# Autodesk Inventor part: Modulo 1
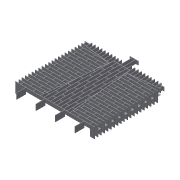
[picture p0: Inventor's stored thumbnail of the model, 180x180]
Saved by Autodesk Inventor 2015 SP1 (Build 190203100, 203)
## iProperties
Created: 2015-04
Part Number: Modulo 1
Material: Generic
Document SubType Name: Modeling
Designer: treina2
Density: 1 g/cm^3
Appearance: Default
Author: treina2
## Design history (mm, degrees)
sketch "Sketch1"
  geometry: L1 (1091.806, 200)-(1091.806, 440) reference; L2 (1091.806, 440)-(1033.806, 440) reference; L3 (1033.806, 440)-(1033.806, 200) reference; L4 (1033.806, 200)-(1091.806, 200) reference; L5 (1159.806, 200)-(1159.806, 315) reference; L6 (1159.806, 315)-(1101.806, 315) reference; L7 (1101.806, 315)-(1101.806, 200) reference; L8 (1101.806, 200)-(1159.806, 200) reference; L9 (1227.806, 200)-(1227.806, 440) reference; L10 (1227.806, 440)-(1169.806, 440) reference; L11 (1169.806, 440)-(1169.806, 200) reference; L12 (1169.806, 200)-(1227.806, 200) reference; L13 (1024, 200)-(1024, 315) reference; L14 (1024, 315)-(966, 315) reference; L15 (966, 315)-(966, 200) reference; L16 (966, 200)-(1024, 200) reference; L17 (1169.806, 1464.632)-(1169.806, 1450) reference; L18 (1169.806, 1450)-(1171.263, 1450) reference; L19 (1284.348, 315)-(1237.806, 315) reference; L20 (1237.806, 315)-(1237.806, 200) reference; L21 (1237.806, 200)-(1295.806, 200) reference; L22 (1259.439, 565)-(1283.351, 325) reference; L23 (1259.439, 565)-(1237.806, 565) reference; L24 (1237.806, 565)-(1237.806, 325) reference; L25 (1237.806, 325)-(1283.351, 325) reference; L26 (1169.806, 1565)-(1177.128, 1492) reference; L27 (1237.806, 1498.938)-(1295.806, 1505.57) reference; L28 (1295.806, 1505.57)-(1295.806, 1686) reference; L29 (1295.806, 1686)-(1237.806, 1686) reference; L30 (1237.806, 1686)-(1237.806, 1498.938) reference; L31 (1159.806, 325)-(1159.806, 565) reference; L32 (1159.806, 565)-(1101.806, 565) reference; L33 (1101.806, 565)-(1101.806, 325) reference; L34 (1101.806, 325)-(1159.806, 325) reference; L35 (1703.806, 1552.224)-(1703.806, 1686) reference; L36 (1703.806, 1686)-(1645.806, 1686) reference; L37 (1645.806, 1686)-(1645.806, 1545.592) reference; L38 (1024, 325)-(1024, 565) reference; L39 (1024, 565)-(966, 565) reference; L40 (966, 565)-(966, 325) reference; L41 (966, 325)-(1024, 325) reference; L42 (1091.806, 450)-(1091.806, 690) reference; L43 (1091.806, 690)-(1033.806, 690) reference; L44 (1033.806, 690)-(1033.806, 450) reference; L45 (1033.806, 450)-(1091.806, 450) reference; L46 (1227.806, 450)-(1227.806, 690) reference; L47 (1227.806, 690)-(1169.806, 690) reference; L48 (1169.806, 690)-(1169.806, 450) reference; L49 (1169.806, 450)-(1227.806, 450) reference; L50 (1159.806, 575)-(1159.806, 815) reference; L51 (1159.806, 815)-(1101.806, 815) reference; L52 (1101.806, 815)-(1101.806, 575) reference; L53 (1101.806, 575)-(1159.806, 575) reference; L54 (1237.806, 782.132)-(1237.806, 575) reference; L55 (1237.806, 575)-(1258.443, 575) reference; L56 (1024, 575)-(1024, 815) reference; L57 (1024, 815)-(966, 815) reference; L58 (966, 815)-(966, 575) reference; L59 (966, 575)-(1024, 575) reference; L60 (1091.806, 700)-(1091.806, 940) reference; L61 (1091.806, 940)-(1033.806, 940) reference; L62 (1033.806, 940)-(1033.806, 700) reference; L63 (1033.806, 700)-(1091.806, 700) reference; L64 (1227.806, 700)-(1227.806, 882.5) reference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; 1 further point
  constraints: 1754 end point, 397 horizontal, 367 vertical, 18 point on line, 953 other
workplane "Work Plane1"
sketch "Sketch2"
  geometry: L1 (1990, 0)-(1600, 0) reference; L2 (1990, 0)-(1880.303, 190) reference; L3 (1765, 190)-(1880.303, 190) reference; L4 (1600, 190)-(1880.303, 190) reference; L5 (1600, 0)-(1600, 190) reference; L6 (1590, 190)-(1590, 0) reference; L7 (1200, 190)-(1590, 190) reference; L8 (1590, 0)-(1200, 0) reference; L9 (1200, 0)-(1200, 190) reference; L10 (1190, 190)-(1190, 0) reference; L11 (1190, 0)-(800, 0) reference; L12 (800, 190)-(1190, 190) reference; L13 (800, 0)-(800, 190) reference; L14 (790, 190)-(790, 0) reference; L15 (400, 190)-(790, 190) reference; L16 (790, 0)-(400, 0) reference; L17 (400, 0)-(400, 190) reference; L18 (390, 190)-(390, 0) reference; L19 (109.697, 190)-(390, 190) reference; L20 (390, 0)-(0, 0) reference; L21 (0, 0)-(109.697, 190) reference; 1 further point
extrude "Extrusion1" new body sketch "Sketch2" distance "d2" = 140 (= BLOCO_PADRAO_LARG); taper "d3" = 0 deg
extrude "Extrusion2" new body sketch "Sketch2" distance "d4" = 140 (= BLOCO_PADRAO_LARG); taper "d5" = 0 deg
extrude "Extrusion3" new body sketch "Sketch2" distance "d6" = 140 (= BLOCO_PADRAO_LARG); taper "d7" = 0 deg
extrude "Extrusion4" new body sketch "Sketch2" distance "d8" = 140 (= BLOCO_PADRAO_LARG); taper "d9" = 0 deg
extrude "Extrusion5" new body sketch "Sketch2" distance "d10" = 140 (= BLOCO_PADRAO_LARG); taper "d11" = 0 deg
extrude "Extrusion6" new body sketch "Sketch1" distance "d12" = 240 (= TIJOLO_PADRAO_COMP); taper "d13" = 0 deg
extrude "Extrusion7" new body sketch "Sketch1" distance "d14" = 240 (= TIJOLO_PADRAO_COMP); taper "d15" = 0 deg
extrude "Extrusion8" new body sketch "Sketch1" distance "d16" = 115 (= TIJOLO_PADRAO_LARG); taper "d17" = 0 deg
extrude "Extrusion9" new body sketch "Sketch1" distance "d18" = 115 (= TIJOLO_PADRAO_LARG); taper "d19" = 0 deg
extrude "Extrusion10" new body sketch "Sketch1" distance "d20" = 115 (= TIJOLO_PADRAO_LARG); taper "d21" = 0 deg
extrude "Extrusion11" new body sketch "Sketch1" distance "d22" = 115 (= TIJOLO_PADRAO_LARG); taper "d23" = 0 deg
extrude "Extrusion12" new body sketch "Sketch1" distance "d24" = 115 (= TIJOLO_PADRAO_LARG); taper "d25" = 0 deg
extrude "Extrusion13" new body sketch "Sketch1" distance "d26" = 240 (= TIJOLO_PADRAO_COMP); taper "d27" = 0 deg
extrude "Extrusion14" new body sketch "Sketch1" distance "d28" = 115 (= TIJOLO_PADRAO_LARG); taper "d29" = 0 deg
extrude "Extrusion15" new body sketch "Sketch1" distance "d30" = 115 (= TIJOLO_PADRAO_LARG); taper "d31" = 0 deg
extrude "Extrusion16" new body sketch "Sketch1" distance "d32" = 115 (= TIJOLO_PADRAO_LARG); taper "d33" = 0 deg
extrude "Extrusion17" new body sketch "Sketch1" distance "d34" = 115 (= TIJOLO_PADRAO_LARG); taper "d35" = 0 deg
extrude "Extrusion18" new body sketch "Sketch1" distance "d36" = 115 (= TIJOLO_PADRAO_LARG); taper "d37" = 0 deg
extrude "Extrusion19" new body sketch "Sketch1" distance "d38" = 115 (= TIJOLO_PADRAO_LARG); taper "d39" = 0 deg
extrude "Extrusion20" new body sketch "Sketch1" distance "d40" = 115 (= TIJOLO_PADRAO_LARG); taper "d41" = 0 deg
extrude "Extrusion21" new body sketch "Sketch1" distance "d42" = 115 (= TIJOLO_PADRAO_LARG); taper "d43" = 0 deg
extrude "Extrusion22" new body sketch "Sketch1" distance "d44" = 115 (= TIJOLO_PADRAO_LARG); taper "d45" = 0 deg
extrude "Extrusion23" new body sketch "Sketch1" distance "d46" = 115 (= TIJOLO_PADRAO_LARG); taper "d47" = 0 deg
extrude "Extrusion24" new body sketch "Sketch1" distance "d48" = 240 (= TIJOLO_PADRAO_COMP); taper "d49" = 0 deg
extrude "Extrusion25" new body sketch "Sketch1" distance "d50" = 115 (= TIJOLO_PADRAO_LARG); taper "d51" = 0 deg
extrude "Extrusion26" new body sketch "Sketch1" distance "d52" = 115 (= TIJOLO_PADRAO_LARG); taper "d53" = 0 deg
extrude "Extrusion27" new body sketch "Sketch1" distance "d54" = 240 (= TIJOLO_PADRAO_COMP); taper "d55" = 0 deg
extrude "Extrusion28" new body sketch "Sketch1" distance "d56" = 115 (= TIJOLO_PADRAO_LARG); taper "d57" = 0 deg
extrude "Extrusion29" new body sketch "Sketch1" distance "d58" = 115 (= TIJOLO_PADRAO_LARG); taper "d59" = 0 deg
extrude "Extrusion30" new body sketch "Sketch1" distance "d60" = 115 (= TIJOLO_PADRAO_LARG); taper "d61" = 0 deg
extrude "Extrusion31" new body sketch "Sketch1" distance "d62" = 115 (= TIJOLO_PADRAO_LARG); taper "d63" = 0 deg
extrude "Extrusion32" new body sketch "Sketch1" distance "d64" = 115 (= TIJOLO_PADRAO_LARG); taper "d65" = 0 deg
extrude "Extrusion33" new body sketch "Sketch1" distance "d66" = 115 (= TIJOLO_PADRAO_LARG); taper "d67" = 0 deg
extrude "Extrusion34" new body sketch "Sketch1" distance "d68" = 115 (= TIJOLO_PADRAO_LARG); taper "d69" = 0 deg
extrude "Extrusion35" new body sketch "Sketch1" distance "d70" = 115 (= TIJOLO_PADRAO_LARG); taper "d71" = 0 deg
extrude "Extrusion36" new body sketch "Sketch1" distance "d72" = 240 (= TIJOLO_PADRAO_COMP); taper "d73" = 0 deg
extrude "Extrusion37" new body sketch "Sketch1" distance "d74" = 115 (= TIJOLO_PADRAO_LARG); taper "d75" = 0 deg
extrude "Extrusion38" new body sketch "Sketch1" distance "d76" = 115 (= TIJOLO_PADRAO_LARG); taper "d77" = 0 deg
extrude "Extrusion39" new body sketch "Sketch1" distance "d78" = 115 (= TIJOLO_PADRAO_LARG); taper "d79" = 0 deg
extrude "Extrusion40" new body sketch "Sketch1" distance "d80" = 115 (= TIJOLO_PADRAO_LARG); taper "d81" = 0 deg
extrude "Extrusion41" new body sketch "Sketch1" distance "d82" = 115 (= TIJOLO_PADRAO_LARG); taper "d83" = 0 deg
extrude "Extrusion42" new body sketch "Sketch1" distance "d84" = 115 (= TIJOLO_PADRAO_LARG); taper "d85" = 0 deg
extrude "Extrusion43" new body sketch "Sketch1" distance "d86" = 115 (= TIJOLO_PADRAO_LARG); taper "d87" = 0 deg
extrude "Extrusion44" new body sketch "Sketch1" distance "d88" = 240 (= TIJOLO_PADRAO_COMP); taper "d89" = 0 deg
extrude "Extrusion45" new body sketch "Sketch1" distance "d90" = 240 (= TIJOLO_PADRAO_COMP); taper "d91" = 0 deg
extrude "Extrusion46" new body sketch "Sketch1" distance "d92" = 240 (= TIJOLO_PADRAO_COMP); taper "d93" = 0 deg
extrude "Extrusion47" new body sketch "Sketch1" distance "d94" = 240 (= TIJOLO_PADRAO_COMP); taper "d95" = 0 deg
extrude "Extrusion48" new body sketch "Sketch1" distance "d96" = 240 (= TIJOLO_PADRAO_COMP); taper "d97" = 0 deg
extrude "Extrusion49" new body sketch "Sketch1" distance "d98" = 115 (= TIJOLO_PADRAO_LARG); taper "d99" = 0 deg
extrude "Extrusion50" new body sketch "Sketch1" distance "d100" = 115 (= TIJOLO_PADRAO_LARG); taper "d101" = 0 deg
extrude "Extrusion51" new body sketch "Sketch1" distance "d102" = 115 (= TIJOLO_PADRAO_LARG); taper "d103" = 0 deg
extrude "Extrusion52" new body sketch "Sketch1" distance "d104" = 115 (= TIJOLO_PADRAO_LARG); taper "d105" = 0 deg
extrude "Extrusion53" new body sketch "Sketch1" distance "d106" = 115 (= TIJOLO_PADRAO_LARG); taper "d107" = 0 deg
extrude "Extrusion54" new body sketch "Sketch1" distance "d108" = 115 (= TIJOLO_PADRAO_LARG); taper "d109" = 0 deg
extrude "Extrusion55" new body sketch "Sketch1" distance "d110" = 115 (= TIJOLO_PADRAO_LARG); taper "d111" = 0 deg
extrude "Extrusion56" new body sketch "Sketch1" distance "d112" = 115 (= TIJOLO_PADRAO_LARG); taper "d113" = 0 deg
extrude "Extrusion57" new body sketch "Sketch1" distance "d114" = 115 (= TIJOLO_PADRAO_LARG); taper "d115" = 0 deg
extrude "Extrusion58" new body sketch "Sketch1" distance "d116" = 115 (= TIJOLO_PADRAO_LARG); taper "d117" = 0 deg
extrude "Extrusion59" new body sketch "Sketch1" distance "d118" = 115 (= TIJOLO_PADRAO_LARG); taper "d119" = 0 deg
extrude "Extrusion60" new body sketch "Sketch1" distance "d120" = 115 (= TIJOLO_PADRAO_LARG); taper "d121" = 0 deg
extrude "Extrusion61" new body sketch "Sketch1" distance "d122" = 115 (= TIJOLO_PADRAO_LARG); taper "d123" = 0 deg
extrude "Extrusion62" new body sketch "Sketch1" distance "d124" = 115 (= TIJOLO_PADRAO_LARG); taper "d125" = 0 deg
extrude "Extrusion63" new body sketch "Sketch1" distance "d126" = 115 (= TIJOLO_PADRAO_LARG); taper "d127" = 0 deg
extrude "Extrusion64" new body sketch "Sketch1" distance "d128" = 115 (= TIJOLO_PADRAO_LARG); taper "d129" = 0 deg
extrude "Extrusion65" new body sketch "Sketch1" distance "d130" = 115 (= TIJOLO_PADRAO_LARG); taper "d131" = 0 deg
extrude "Extrusion66" new body sketch "Sketch1" distance "d132" = 115 (= TIJOLO_PADRAO_LARG); taper "d133" = 0 deg
extrude "Extrusion67" new body sketch "Sketch1" distance "d134" = 115 (= TIJOLO_PADRAO_LARG); taper "d135" = 0 deg
extrude "Extrusion68" new body sketch "Sketch1" distance "d136" = 115 (= TIJOLO_PADRAO_LARG); taper "d137" = 0 deg
extrude "Extrusion69" new body sketch "Sketch1" distance "d138" = 240 (= TIJOLO_PADRAO_COMP); taper "d139" = 0 deg
extrude "Extrusion70" new body sketch "Sketch1" distance "d140" = 240 (= TIJOLO_PADRAO_COMP); taper "d141" = 0 deg
extrude "Extrusion71" new body sketch "Sketch1" distance "d142" = 240 (= TIJOLO_PADRAO_COMP); taper "d143" = 0 deg
extrude "Extrusion72" new body sketch "Sketch1" distance "d144" = 240 (= TIJOLO_PADRAO_COMP); taper "d145" = 0 deg
extrude "Extrusion73" new body sketch "Sketch1" distance "d146" = 240 (= TIJOLO_PADRAO_COMP); taper "d147" = 0 deg
extrude "Extrusion74" new body sketch "Sketch1" distance "d148" = 240 (= TIJOLO_PADRAO_COMP); taper "d149" = 0 deg
extrude "Extrusion75" new body sketch "Sketch1" distance "d150" = 240 (= TIJOLO_PADRAO_COMP); taper "d151" = 0 deg
extrude "Extrusion76" new body sketch "Sketch1" distance "d152" = 240 (= TIJOLO_PADRAO_COMP); taper "d153" = 0 deg
extrude "Extrusion77" new body sketch "Sketch1" distance "d154" = 240 (= TIJOLO_PADRAO_COMP); taper "d155" = 0 deg
extrude "Extrusion78" new body sketch "Sketch1" distance "d156" = 115 (= TIJOLO_PADRAO_LARG); taper "d157" = 0 deg
extrude "Extrusion79" new body sketch "Sketch1" distance "d158" = 115 (= TIJOLO_PADRAO_LARG); taper "d159" = 0 deg
extrude "Extrusion80" new body sketch "Sketch1" distance "d160" = 115 (= TIJOLO_PADRAO_LARG); taper "d161" = 0 deg
extrude "Extrusion81" new body sketch "Sketch1" distance "d162" = 115 (= TIJOLO_PADRAO_LARG); taper "d163" = 0 deg
extrude "Extrusion82" new body sketch "Sketch1" distance "d164" = 115 (= TIJOLO_PADRAO_LARG); taper "d165" = 0 deg
extrude "Extrusion83" new body sketch "Sketch1" distance "d166" = 115 (= TIJOLO_PADRAO_LARG); taper "d167" = 0 deg
extrude "Extrusion84" new body sketch "Sketch1" distance "d168" = 115 (= TIJOLO_PADRAO_LARG); taper "d169" = 0 deg
extrude "Extrusion85" new body sketch "Sketch1" distance "d170" = 115 (= TIJOLO_PADRAO_LARG); taper "d171" = 0 deg
extrude "Extrusion86" new body sketch "Sketch1" distance "d172" = 115 (= TIJOLO_PADRAO_LARG); taper "d173" = 0 deg
extrude "Extrusion87" new body sketch "Sketch1" distance "d174" = 115 (= TIJOLO_PADRAO_LARG); taper "d175" = 0 deg
extrude "Extrusion88" new body sketch "Sketch1" distance "d176" = 115 (= TIJOLO_PADRAO_LARG); taper "d177" = 0 deg
extrude "Extrusion89" new body sketch "Sketch1" distance "d178" = 115 (= TIJOLO_PADRAO_LARG); taper "d179" = 0 deg
extrude "Extrusion90" new body sketch "Sketch1" distance "d180" = 115 (= TIJOLO_PADRAO_LARG); taper "d181" = 0 deg
pattern_linear "Rectangular Pattern1" dims "d184" = 136 (= 2 x TIJOLO_PADRAO_PROF + 2 x GAP)
pattern_linear "Rectangular Pattern2" dims "d187" = 136 (= 2 x TIJOLO_PADRAO_PROF + 2 x GAP)
pattern_linear "Rectangular Pattern3" dims "d190" = 136 (= 2 x TIJOLO_PADRAO_PROF + 2 x GAP)
extrude "Extrusion91" new body sketch "Sketch1" distance "d191" = 115 (= TIJOLO_PADRAO_LARG); taper "d192" = 0 deg
extrude "Extrusion92" new body sketch "Sketch1" distance "d193" = 115 (= TIJOLO_PADRAO_LARG); taper "d194" = 0 deg
extrude "Extrusion93" new body sketch "Sketch1" distance "d195" = 115 (= TIJOLO_PADRAO_LARG); taper "d196" = 0 deg
extrude "Extrusion94" new body sketch "Sketch1" distance "d197" = 115 (= TIJOLO_PADRAO_LARG); taper "d198" = 0 deg
extrude "Extrusion95" new body sketch "Sketch1" distance "d199" = 115 (= TIJOLO_PADRAO_LARG); taper "d200" = 0 deg
extrude "Extrusion96" new body sketch "Sketch1" distance "d201" = 115 (= TIJOLO_PADRAO_LARG); taper "d202" = 0 deg
extrude "Extrusion97" new body sketch "Sketch1" distance "d203" = 115 (= TIJOLO_PADRAO_LARG); taper "d204" = 0 deg
extrude "Extrusion98" new body sketch "Sketch1" distance "d205" = 115 (= TIJOLO_PADRAO_LARG); taper "d206" = 0 deg
extrude "Extrusion99" new body sketch "Sketch1" distance "d207" = 115 (= TIJOLO_PADRAO_LARG); taper "d208" = 0 deg
extrude "Extrusion100" new body sketch "Sketch1" distance "d209" = 115 (= TIJOLO_PADRAO_LARG); taper "d210" = 0 deg
extrude "Extrusion101" new body sketch "Sketch1" distance "d211" = 115 (= TIJOLO_PADRAO_LARG); taper "d212" = 0 deg
extrude "Extrusion102" new body sketch "Sketch1" distance "d213" = 115 (= TIJOLO_PADRAO_LARG); taper "d214" = 0 deg
extrude "Extrusion103" new body sketch "Sketch1" distance "d215" = 115 (= TIJOLO_PADRAO_LARG); taper "d216" = 0 deg
extrude "Extrusion104" new body sketch "Sketch1" distance "d217" = 115 (= TIJOLO_PADRAO_LARG); taper "d218" = 0 deg
extrude "Extrusion105" new body sketch "Sketch1" distance "d219" = 115 (= TIJOLO_PADRAO_LARG); taper "d220" = 0 deg
extrude "Extrusion106" new body sketch "Sketch1" distance "d221" = 115 (= TIJOLO_PADRAO_LARG); taper "d222" = 0 deg
extrude "Extrusion107" new body sketch "Sketch1" distance "d223" = 115 (= TIJOLO_PADRAO_LARG); taper "d224" = 0 deg
extrude "Extrusion108" new body sketch "Sketch1" distance "d225" = 115 (= TIJOLO_PADRAO_LARG); taper "d226" = 0 deg
extrude "Extrusion109" new body sketch "Sketch1" distance "d227" = 240 (= TIJOLO_PADRAO_COMP); taper "d228" = 0 deg
extrude "Extrusion110" new body sketch "Sketch1" distance "d229" = 240 (= TIJOLO_PADRAO_COMP); taper "d230" = 0 deg
workplane "Work Plane2"
sketch "Sketch3"
  geometry: L1 (898.194, 1575)-(898.194, 1815) reference; L2 (898.194, 1815)-(956.194, 1815) reference; L3 (956.194, 1815)-(956.194, 1575) reference; L4 (956.194, 1575)-(898.194, 1575) reference; L5 (966, 1575)-(966, 1815) reference; L6 (1024, 1575)-(966, 1575) reference; L7 (1024, 1815)-(1024, 1575) reference; L8 (1033.806, 1575)-(1033.806, 1815) reference; L9 (1091.806, 1575)-(1033.806, 1575) reference; L10 (1091.806, 1815)-(1091.806, 1575) reference; L11 (1033.806, 1815)-(1091.806, 1815) reference; L12 (966, 1815)-(1024, 1815) reference; 1 further point
extrude "Extrusion111" new body sketch "Sketch3" distance "d232" = 115 (= AMAR_PADRAO_LARG); taper "d233" = 0 deg
extrude "Extrusion112" new body sketch "Sketch3" distance "d234" = 115 (= AMAR_PADRAO_LARG); taper "d235" = 0 deg
extrude "Extrusion113" new body sketch "Sketch3" distance "d236" = 115 (= AMAR_PADRAO_LARG); taper "d237" = 0 deg
workplane "Work Plane3"
sketch "Sketch4"
  geometry: L1 (1081.579, 1883)-(908.421, 1883) reference; L2 (898.194, 1825)-(908.421, 1883) reference; L3 (898.194, 1825)-(1091.806, 1825) reference; L4 (1091.806, 1825)-(1081.579, 1883) reference; 1 further point
extrude "Extrusion114" new body sketch "Sketch4" distance "d239" = 115 (= AMAR_PADRAO_LARG); taper "d240" = 0 deg
workplane "Work Plane4"
sketch "Sketch5"
  geometry: L1 (1091.806, 200)-(1091.806, 440) reference; L2 (1091.806, 440)-(1033.806, 440) reference; L3 (1033.806, 440)-(1033.806, 200) reference; L4 (1033.806, 200)-(1091.806, 200) reference; L5 (1159.806, 200)-(1159.806, 315) reference; L6 (1159.806, 315)-(1101.806, 315) reference; L7 (1101.806, 315)-(1101.806, 200) reference; L8 (1101.806, 200)-(1159.806, 200) reference; L9 (1227.806, 200)-(1227.806, 440) reference; L10 (1227.806, 440)-(1169.806, 440) reference; L11 (1169.806, 440)-(1169.806, 200) reference; L12 (1169.806, 200)-(1227.806, 200) reference; L13 (1024, 200)-(1024, 315) reference; L14 (1024, 315)-(966, 315) reference; L15 (966, 315)-(966, 200) reference; L16 (966, 200)-(1024, 200) reference; L17 (1169.806, 1464.632)-(1169.806, 1450) reference; L18 (1169.806, 1450)-(1171.263, 1450) reference; L19 (1284.348, 315)-(1237.806, 315) reference; L20 (1237.806, 315)-(1237.806, 200) reference; L21 (1237.806, 200)-(1295.806, 200) reference; L22 (1259.439, 565)-(1283.351, 325) reference; L23 (1259.439, 565)-(1237.806, 565) reference; L24 (1237.806, 565)-(1237.806, 325) reference; L25 (1237.806, 325)-(1283.351, 325) reference; L26 (1169.806, 1565)-(1177.128, 1492) reference; L27 (1237.806, 1498.938)-(1295.806, 1505.57) reference; L28 (1295.806, 1505.57)-(1295.806, 1686) reference; L29 (1295.806, 1686)-(1237.806, 1686) reference; L30 (1237.806, 1686)-(1237.806, 1498.938) reference; L31 (1159.806, 325)-(1159.806, 565) reference; L32 (1159.806, 565)-(1101.806, 565) reference; L33 (1101.806, 565)-(1101.806, 325) reference; L34 (1101.806, 325)-(1159.806, 325) reference; L35 (1703.806, 1552.224)-(1703.806, 1686) reference; L36 (1703.806, 1686)-(1645.806, 1686) reference; L37 (1645.806, 1686)-(1645.806, 1545.592) reference; L38 (1024, 325)-(1024, 565) reference; L39 (1024, 565)-(966, 565) reference; L40 (966, 565)-(966, 325) reference; L41 (966, 325)-(1024, 325) reference; L42 (1091.806, 450)-(1091.806, 690) reference; L43 (1091.806, 690)-(1033.806, 690) reference; L44 (1033.806, 690)-(1033.806, 450) reference; L45 (1033.806, 450)-(1091.806, 450) reference; L46 (1227.806, 450)-(1227.806, 690) reference; L47 (1227.806, 690)-(1169.806, 690) reference; L48 (1169.806, 690)-(1169.806, 450) reference; L49 (1169.806, 450)-(1227.806, 450) reference; L50 (1159.806, 575)-(1159.806, 815) reference; L51 (1159.806, 815)-(1101.806, 815) reference; L52 (1101.806, 815)-(1101.806, 575) reference; L53 (1101.806, 575)-(1159.806, 575) reference; L54 (1237.806, 782.132)-(1237.806, 575) reference; L55 (1237.806, 575)-(1258.443, 575) reference; L56 (1024, 575)-(1024, 815) reference; L57 (1024, 815)-(966, 815) reference; L58 (966, 815)-(966, 575) reference; L59 (966, 575)-(1024, 575) reference; L60 (1091.806, 700)-(1091.806, 940) reference; L61 (1091.806, 940)-(1033.806, 940) reference; L62 (1033.806, 940)-(1033.806, 700) reference; L63 (1033.806, 700)-(1091.806, 700) reference; L64 (1227.806, 700)-(1227.806, 882.5) reference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; 2 further points
  constraints: 1754 end point, 397 horizontal, 367 vertical, 18 point on line, 953 other
extrude "Extrusion115" new body sketch "Sketch5" distance "d242" = 115 (= AMAR_PADRAO_LARG); taper "d243" = 0 deg
extrude "Extrusion116" new body sketch "Sketch5" distance "d244" = 115 (= AMAR_PADRAO_LARG); taper "d245" = 0 deg
extrude "Extrusion117" new body sketch "Sketch5" distance "d246" = 115 (= AMAR_PADRAO_LARG); taper "d247" = 0 deg
extrude "Extrusion118" new body sketch "Sketch5" distance "d248" = 115 (= AMAR_PADRAO_LARG); taper "d249" = 0 deg
extrude "Extrusion119" new body sketch "Sketch5" distance "d250" = 115 (= AMAR_PADRAO_LARG); taper "d251" = 0 deg
extrude "Extrusion120" new body sketch "Sketch5" distance "d252" = 115 (= AMAR_PADRAO_LARG); taper "d253" = 0 deg
extrude "Extrusion121" new body sketch "Sketch5" distance "d254" = 115 (= AMAR_PADRAO_LARG); taper "d255" = 0 deg
extrude "Extrusion122" new body sketch "Sketch5" distance "d256" = 115 (= AMAR_PADRAO_LARG); taper "d257" = 0 deg
extrude "Extrusion123" new body sketch "Sketch5" distance "d258" = 115 (= AMAR_PADRAO_LARG); taper "d259" = 0 deg
extrude "Extrusion124" new body sketch "Sketch5" distance "d260" = 115 (= AMAR_PADRAO_LARG); taper "d261" = 0 deg
extrude "Extrusion125" new body sketch "Sketch5" distance "d262" = 115 (= AMAR_PADRAO_LARG); taper "d263" = 0 deg
extrude "Extrusion126" new body sketch "Sketch5" distance "d264" = 115 (= AMAR_PADRAO_LARG); taper "d265" = 0 deg
extrude "Extrusion127" new body sketch "Sketch5" distance "d266" = 115 (= AMAR_PADRAO_LARG); taper "d267" = 0 deg
extrude "Extrusion128" new body sketch "Sketch5" distance "d268" = 115 (= AMAR_PADRAO_LARG); taper "d269" = 0 deg
extrude "Extrusion129" new body sketch "Sketch5" distance "d270" = 115 (= AMAR_PADRAO_LARG); taper "d271" = 0 deg
extrude "Extrusion130" new body sketch "Sketch5" distance "d272" = 115 (= AMAR_PADRAO_LARG); taper "d273" = 0 deg
extrude "Extrusion131" new body sketch "Sketch5" distance "d274" = 115 (= AMAR_PADRAO_LARG); taper "d275" = 0 deg
extrude "Extrusion132" new body sketch "Sketch5" distance "d276" = 115 (= AMAR_PADRAO_LARG); taper "d277" = 0 deg
extrude "Extrusion133" new body sketch "Sketch5" distance "d278" = 115 (= AMAR_PADRAO_LARG); taper "d279" = 0 deg
extrude "Extrusion134" new body sketch "Sketch5" distance "d280" = 115 (= AMAR_PADRAO_LARG); taper "d281" = 0 deg
extrude "Extrusion135" new body sketch "Sketch5" distance "d282" = 115 (= AMAR_PADRAO_LARG); taper "d283" = 0 deg
extrude "Extrusion136" new body sketch "Sketch5" distance "d284" = 115 (= AMAR_PADRAO_LARG); taper "d285" = 0 deg
extrude "Extrusion137" new body sketch "Sketch5" distance "d286" = 115 (= AMAR_PADRAO_LARG); taper "d287" = 0 deg
extrude "Extrusion138" new body sketch "Sketch5" distance "d288" = 115 (= AMAR_PADRAO_LARG); taper "d289" = 0 deg
extrude "Extrusion139" new body sketch "Sketch5" distance "d290" = 115 (= AMAR_PADRAO_LARG); taper "d291" = 0 deg
extrude "Extrusion140" new body sketch "Sketch5" distance "d292" = 115 (= AMAR_PADRAO_LARG); taper "d293" = 0 deg
extrude "Extrusion141" new body sketch "Sketch5" distance "d294" = 115 (= AMAR_PADRAO_LARG); taper "d295" = 0 deg
extrude "Extrusion142" new body sketch "Sketch5" distance "d296" = 115 (= AMAR_PADRAO_LARG); taper "d297" = 0 deg
extrude "Extrusion143" new body sketch "Sketch5" distance "d298" = 115 (= AMAR_PADRAO_LARG); taper "d299" = 0 deg
extrude "Extrusion144" new body sketch "Sketch5" distance "d300" = 115 (= AMAR_PADRAO_LARG); taper "d301" = 0 deg
extrude "Extrusion145" new body sketch "Sketch5" distance "d302" = 115 (= AMAR_PADRAO_LARG); taper "d303" = 0 deg
extrude "Extrusion146" new body sketch "Sketch5" distance "d304" = 115 (= AMAR_PADRAO_LARG); taper "d305" = 0 deg
extrude "Extrusion147" new body sketch "Sketch5" distance "d306" = 115 (= AMAR_PADRAO_LARG); taper "d307" = 0 deg
extrude "Extrusion148" new body sketch "Sketch5" distance "d308" = 115 (= AMAR_PADRAO_LARG); taper "d309" = 0 deg
extrude "Extrusion149" new body sketch "Sketch5" distance "d310" = 115 (= AMAR_PADRAO_LARG); taper "d311" = 0 deg
extrude "Extrusion150" new body sketch "Sketch5" distance "d312" = 115 (= AMAR_PADRAO_LARG); taper "d313" = 0 deg
extrude "Extrusion151" new body sketch "Sketch5" distance "d314" = 115 (= AMAR_PADRAO_LARG); taper "d315" = 0 deg
extrude "Extrusion152" new body sketch "Sketch5" distance "d316" = 115 (= AMAR_PADRAO_LARG); taper "d317" = 0 deg
extrude "Extrusion153" new body sketch "Sketch5" distance "d318" = 115 (= AMAR_PADRAO_LARG); taper "d319" = 0 deg
extrude "Extrusion154" new body sketch "Sketch5" distance "d320" = 115 (= AMAR_PADRAO_LARG); taper "d321" = 0 deg
extrude "Extrusion155" new body sketch "Sketch5" distance "d322" = 115 (= AMAR_PADRAO_LARG); taper "d323" = 0 deg
extrude "Extrusion156" new body sketch "Sketch5" distance "d324" = 115 (= AMAR_PADRAO_LARG); taper "d325" = 0 deg
extrude "Extrusion157" new body sketch "Sketch5" distance "d326" = 115 (= AMAR_PADRAO_LARG); taper "d327" = 0 deg
extrude "Extrusion158" new body sketch "Sketch5" distance "d328" = 115 (= AMAR_PADRAO_LARG); taper "d329" = 0 deg
extrude "Extrusion159" new body sketch "Sketch5" distance "d330" = 115 (= AMAR_PADRAO_LARG); taper "d331" = 0 deg
extrude "Extrusion160" new body sketch "Sketch5" distance "d332" = 115 (= AMAR_PADRAO_LARG); taper "d333" = 0 deg
extrude "Extrusion161" new body sketch "Sketch5" distance "d334" = 115 (= AMAR_PADRAO_LARG); taper "d335" = 0 deg
extrude "Extrusion162" new body sketch "Sketch5" distance "d336" = 115 (= AMAR_PADRAO_LARG); taper "d337" = 0 deg
extrude "Extrusion163" new body sketch "Sketch5" distance "d338" = 115 (= AMAR_PADRAO_LARG); taper "d339" = 0 deg
extrude "Extrusion164" new body sketch "Sketch5" distance "d340" = 115 (= AMAR_PADRAO_LARG); taper "d341" = 0 deg
extrude "Extrusion165" new body sketch "Sketch5" distance "d342" = 115 (= AMAR_PADRAO_LARG); taper "d343" = 0 deg
extrude "Extrusion166" new body sketch "Sketch5" distance "d344" = 115 (= AMAR_PADRAO_LARG); taper "d345" = 0 deg
extrude "Extrusion167" new body sketch "Sketch5" distance "d346" = 115 (= AMAR_PADRAO_LARG); taper "d347" = 0 deg
extrude "Extrusion168" new body sketch "Sketch5" distance "d348" = 115 (= AMAR_PADRAO_LARG); taper "d349" = 0 deg
extrude "Extrusion169" new body sketch "Sketch5" distance "d350" = 115 (= AMAR_PADRAO_LARG); taper "d351" = 0 deg
extrude "Extrusion170" new body sketch "Sketch5" distance "d352" = 115 (= AMAR_PADRAO_LARG); taper "d353" = 0 deg
extrude "Extrusion171" new body sketch "Sketch5" distance "d354" = 115 (= AMAR_PADRAO_LARG); taper "d355" = 0 deg
extrude "Extrusion172" new body sketch "Sketch5" distance "d356" = 115 (= AMAR_PADRAO_LARG); taper "d357" = 0 deg
extrude "Extrusion173" new body sketch "Sketch5" distance "d358" = 115 (= AMAR_PADRAO_LARG); taper "d359" = 0 deg
extrude "Extrusion174" new body sketch "Sketch5" distance "d360" = 115 (= AMAR_PADRAO_LARG); taper "d361" = 0 deg
extrude "Extrusion175" new body sketch "Sketch5" distance "d362" = 115 (= AMAR_PADRAO_LARG); taper "d363" = 0 deg
extrude "Extrusion176" new body sketch "Sketch5" distance "d364" = 115 (= AMAR_PADRAO_LARG); taper "d365" = 0 deg
extrude "Extrusion177" new body sketch "Sketch5" distance "d366" = 115 (= AMAR_PADRAO_LARG); taper "d367" = 0 deg
extrude "Extrusion178" new body sketch "Sketch5" distance "d368" = 115 (= AMAR_PADRAO_LARG); taper "d369" = 0 deg
extrude "Extrusion179" new body sketch "Sketch5" distance "d370" = 115 (= AMAR_PADRAO_LARG); taper "d371" = 0 deg
extrude "Extrusion180" new body sketch "Sketch5" distance "d372" = 115 (= AMAR_PADRAO_LARG); taper "d373" = 0 deg
extrude "Extrusion181" new body sketch "Sketch5" distance "d374" = 115 (= AMAR_PADRAO_LARG); taper "d375" = 0 deg
extrude "Extrusion182" new body sketch "Sketch5" distance "d376" = 115 (= AMAR_PADRAO_LARG); taper "d377" = 0 deg
workplane "Work Plane5"
sketch "Sketch6"
  geometry: L1 (-167.194, 1492)-(-282.194, 1492); L2 (-282.194, 1492)-(-282.194, 1550); L3 (-282.194, 1550)-(-167.194, 1550); L4 (-167.194, 1550)-(-167.194, 1492); 1 further point
  constraints: 8 end point, 2 parallel, 1 horizontal, 1 perpendicular
  dimensions: "d379" = 58 distance of L3.end L1.start (= TIJOLO_PADRAO_PROF); "d380" = 115 distance of L1.start L1.end (= TIJOLO_PADRAO_LARG)
extrude "Extrusion183" new body sketch "Sketch6" distance "d381" = 115 (= AMAR_PADRAO_LARG); taper "d382" = 0 deg
pattern_linear "Rectangular Pattern4" dims "d385" = 136 (= 2 x TIJOLO_PADRAO_PROF + 2 x GAP)
sketch "Sketch7"
  geometry: L1 (-1822.806, 1492)-(-1707.806, 1492); L2 (-1707.806, 1492)-(-1707.806, 1550); L3 (-1707.806, 1550)-(-1822.806, 1550); L4 (-1822.806, 1550)-(-1822.806, 1492); 1 further point
  constraints: 8 end point, 2 parallel, 1 horizontal, 1 perpendicular
  dimensions: "d386" = 115 distance of L2.end L3.end (= TIJOLO_PADRAO_LARG); "d387" = 58 distance of L3.end L1.start (= TIJOLO_PADRAO_PROF)
extrude "Extrusion184" new body sketch "Sketch7" distance "d388" = 115 (= AMAR_PADRAO_LARG); taper "d389" = 0 deg
pattern_linear "Rectangular Pattern5" dims "d392" = 136 (= 2 x TIJOLO_PADRAO_PROF + 2 x GAP)
workplane "Work Plane6"
sketch "Sketch8"
  geometry: L1 (0, 0)-(0, -240) reference; L2 (115, -240)-(0, -240); L3 (0, -240)-(0, -160); L4 (0, -160)-(115, -160); L5 (115, -160)-(115, -240); L6 (222.806, -150)-(-167.194, -150) reference; 1 further point
  constraints: 8 end point, 2 parallel, 1 horizontal, 1 perpendicular, 1 point on line
  dimensions: "d394" = 10 distance between parallel lines of L6 L4
extrude "Extrusion185" new body sketch "Sketch8" stored distance "d395" = 115 (= AMAR_PADRAO_LARG); taper "d396" = 0 deg
sketch "Sketch9"
  geometry: L1 (1540.611, 0)-(1540.611, -240) reference; L2 (1655.611, -240)-(1540.611, -240); L3 (1540.611, -240)-(1540.611, -160); L4 (1540.611, -160)-(1655.611, -160); L5 (1655.611, -160)-(1655.611, -240); L6 (1822.806, -150)-(1432.806, -150) reference; 1 further point
  constraints: 8 end point, 2 parallel, 1 horizontal, 1 perpendicular, 1 point on line
  dimensions: "d397" = 10 distance between parallel lines of L6 L4
extrude "Extrusion186" new body sketch "Sketch9" stored distance "d398" = 115 (= AMAR_PADRAO_LARG); taper "d399" = 0 deg
sketch "Sketch10"
  geometry: L1 (-10, 0)-(-400, 0) reference; L2 (-10, -140)-(-400, -140) reference; L3 (-1050, -10)-(640, -10); L4 (640, -10)-(640, -130); L5 (640, -130)-(-1050, -130); L6 (-1050, -130)-(-1050, -10); L7 (-1200, 0)-(-1200, -140) reference; L8 (790, 0)-(790, -140) reference; 1 further point
  constraints: 8 end point, 2 parallel, 1 horizontal, 1 perpendicular
  dimensions: "d400" = 10 distance between parallel lines of L1 L3; "d401" = 10 distance between parallel lines of L5 L2 (= d400); "d402" = 150 distance between parallel lines of L8 L4; "d403" = 150 distance between parallel lines of L7 L6 (= d402)
extrude "Extrusion187" new body sketch "Sketch10" distance "d404" = 190; taper "d405" = 0 deg
sketch "Sketch11"
  geometry: L1 (105.855, -10)-(247.806, -10) reference; L2 (-108.194, 95)-(-166.194, 95) reference; L3 (612.806, 10)-(-1022.806, 10); L4 (-1022.806, 10)-(-1022.806, 85); L5 (-1022.806, 85)-(612.806, 85); L6 (612.806, 85)-(612.806, 10); L7 (390, 0)-(0, 0) reference; L8 (622.806, -10)-(622.806, 230) reference; L9 (-1032.806, -10)-(-1032.806, 230) reference; 1 further point
  constraints: 8 end point, 2 parallel, 1 horizontal, 1 perpendicular
  dimensions: "d406" = 10 distance between parallel lines of L7 L3; "d407" = 10 distance between parallel lines of L2 L5 (= d406); "d408" = 10 distance between parallel lines of L9 L4 (= d406); "d409" = 10 distance between parallel lines of L8 L6 (= d406)
extrude "Extrusion188" join sketch "Sketch11" distance "d410" = 1481; taper "d411" = 0 deg
sketch "Sketch12"
  geometry: L1 (-108.194, -5)-(-108.194, 110) reference; L2 (-301.806, -5)-(-301.806, 110) reference; L3 (612.806, 85)-(-1022.806, 85) reference; L4 (-1022.806, 10)-(612.806, 10) reference; L5 (-1050, 10)-(640, 10) reference; L6 (-118.194, 10)-(-291.806, 10); L7 (-291.806, 10)-(-291.806, 85); L8 (-291.806, 85)-(-118.194, 85); L9 (-118.194, 85)-(-118.194, 10); 1 further point
  constraints: 8 end point, 2 parallel, 2 point on line, 1 horizontal, 1 perpendicular
  dimensions: "d412" = 10 distance between parallel lines of L7 L2; "d413" = 10 distance between parallel lines of L1 L9 (= d412)
extrude "Extrusion189" join sketch "Sketch12" distance "d414" = 155; taper "d415" = 0 deg
sketch "Sketch13"
  geometry: L1 (105, 1360)-(-10, 1360) reference; L2 (105, 1302)-(105, 1360) reference; L3 (-10, 1360)-(-10, 1302) reference; L4 (1645.611, 1360)-(1530.611, 1360) reference; L5 (1645.611, 1302)-(1645.611, 1360) reference; L6 (1530.611, 1360)-(1530.611, 1302) reference; L7 (0, 0)-(0, 1481) reference; L8 (1635.611, 0)-(1635.611, 1481) reference; L9 (0, 0)-(95, 0); L10 (95, 0)-(95, 1360); L11 (95, 1360)-(0, 1360); L12 (0, 1360)-(0, 0); L13 (1635.611, 0)-(1540.611, 0); L14 (1540.611, 0)-(1540.611, 1360); L15 (1540.611, 1360)-(1635.611, 1360); L16 (1635.611, 1360)-(1635.611, 0); 1 further point
  constraints: 16 end point, 4 parallel, 2 horizontal, 2 perpendicular, 2 point on line
  dimensions: "d416" = 10 distance between parallel lines of L14 L6; "d417" = 10 distance between parallel lines of L2 L10 (= d416)
extrude "Extrusion190" join sketch "Sketch13" distance "d418" = 140; taper "d419" = 0 deg
combine "Combine1"
  node "M1.1"
  node "M1.2"
  node "M1.3"
  node "M1.4"
  node "M1.5"
  node "M1.6"
  node "M1.7"
  node "M1.8"
  node "M1.9"
  node "M1.10"
  node "M1.11"
  node "M1.12"
  node "M1.13"
  node "M1.14"
  node "M1.15"
  node "M1.16"
  node "M1.17"
  node "M1.18"
  node "M1.19"
  node "M1.20"
  node "M1.21"
  node "M1.22"
  node "M1.23"
  node "M1.24"
  node "M1.25"
  node "M1.26"
  node "M1.27"
  node "M1.28"
  node "M1.29"
  node "M1.30"
  node "M1.31"
  node "M1.32"
  node "M1.33"
  node "M1.34"
  node "M1.35"
  node "M1.36"
  node "M1.37"
  node "M1.38"
  node "M1.39"
  node "M1.40"
  node "M1.41"
  node "M1.42"
  node "M1.43"
  node "M1.44"
  node "M1.45"
  node "M1.46"
  node "M1.47"
  node "M1.48"
  node "M1.49"
  node "M1.50"
  node "M1.51"
  node "M1.52"
  node "M1.53"
  node "M1.54"
  node "M1.55"
  node "M1.56"
  node "M1.57"
  node "M1.58"
  node "M1.59"
  node "M1.60"
  node "M1.61"
  node "M1.62"
  node "M1.63"
  node "M1.64"
  node "M1.65"
  node "M1.66"
  node "M1.67"
  node "M1.68"
  node "M1.69"
  node "M1.70"
  node "M1.71"
  node "M1.72"
  node "M1.73"
  node "M1.74"
  node "M1.75"
  node "M1.76"
  node "M1.77"
  node "M1.78"
  node "M1.79"
  node "M1.80"
  node "M1.81"
  node "M1.82"
  node "M1.83"
  node "M1.84"
  node "M1.85"
  node "M1.86"
  node "M1.87"
  node "M1.88"
  node "M1.89"
  node "M1.90"
  node "M1.91"
  node "M1.92"
  node "M1.93"
  node "M1.94"
  node "M1.95"
  node "M1.96"
  node "M1.97"
  node "M1.98"
  node "M1.99"
  node "M1.100"
  node "M1.101"
  node "M1.102"
  node "M1.103"
  node "M1.104"
  node "M1.105"
  node "M1.106"
  node "M1.107"
  node "M1.108"
  node "M1.109"
  node "M1.110"
  node "M1.111"
  node "M1.112"
  node "M1.113"
  node "M1.114"
  node "M1.115"
  node "M1.116"
  node "M1.117"
  node "M1.118"
  node "M1.119"
  node "M1.120"
  node "M1.121"
  node "M1.122"
  node "M1.123"
  node "M1.124"
  node "M1.125"
  node "M1.126"
  node "M1.127"
  node "M1.128"
  node "M1.129"
  node "M1.130"
  node "M1.131"
  node "M1.132"
  node "M1.133"
  node "M1.134"
  node "M1.135"
  node "M1.136"
  node "M1.137"
  node "M1.138"
  node "M1.139"
  node "M1.140"
  node "M1.141"
  node "M1.142"
  node "M1.143"
  node "M1.144"
  node "M1.145"
  node "M1.146"
  node "M1.147"
  node "M1.148"
  node "M1.149"
  node "M1.150"
  node "M1.151"
  node "M1.152"
  node "M1.153"
  node "M1.154"
  node "M1.155"
  node "M1.156"
  node "M1.157"
  node "M1.158"
  node "M1.159"
  node "M1.160"
  node "M1.161"
  node "M1.162"
  node "M1.163"
  node "M1.164"
  node "M1.165"
  node "M1.166"
  node "M1.167"
  node "M1.168"
  node "M1.169"
  node "M1.170"
  node "M1.171"
  node "M1.172"
  node "M1.173"
  node "M1.174"
  node "M1.175"
  node "M1.176"
  node "M1.177"
  node "M1.178"
  node "M1.179"
  node "M1.180"
  node "M1.181"
  node "M1.182"
  node "M1.183"
  node "M1.184"
  node "M1.185"
  node "M1.186"
  node "M1.187"
  node "M1.188"
  node "M1.189"
  node "M1.190"
  node "M1.191"
  node "M1.192"
  node "M1.193"
  node "M1.194"
  node "M1.195"
  node "M1.196"
  node "M1.197"
  node "M1.198"
  node "M1.199"
  node "M1.200"
  node "M1.201"
  node "M1.202"
  node "M1.203"
  node "M1.204"
  node "M1.205"
  node "M1.206"
  node "M1.207"
  node "M1.208"
  node "M1.209"
  node "M1.210"
  node "M1.211"
  node "M1.212"
  node "M1.213"
  node "M1.214"
  node "M1.215"
  node "M1.216"
  node "M1.217"
  node "M1.218"
  node "M1.219"
  node "M1.220"
  node "M1.221"
  node "M1.222"
  node "M1.223"
  node "M1.224"
delete_face "Delete Face1"
feature "Pattern of M1.90:1"
feature "Pattern of M1.90:2"
feature "Pattern of M1.90:3"
feature "Pattern of M1.90:4"
feature "Pattern of M1.90:5"
feature "Pattern of M1.90:6"
feature "Pattern of M1.90:7"
feature "Pattern of M1.90:8"
feature "Pattern of M1.90:9"
feature "Pattern of M1.90:10"
feature "Pattern of M1.90:11"
feature "Pattern of M1.90:12"
feature "Pattern of M1.90:13"
feature "Pattern of M1.90:14"
feature "Pattern of M1.90:15"
feature "Pattern of M1.90:16"
feature "Pattern of M1.90:17"
feature "Pattern of M1.90:18"
feature "Pattern of M1.90:19"
feature "Pattern of M1.90:20"
feature "Pattern of M1.90:21"
feature "Pattern of M1.204:22"
feature "Pattern of M1.204:23"
feature "Pattern of M1.204:24"
feature "Pattern of M1.204:25"
feature "Pattern of M1.204:26"
feature "Pattern of M1.204:27"
feature "Pattern of M1.204:28"
feature "Pattern of M1.204:29"
feature "Pattern of M1.204:30"
feature "Pattern of M1.214:31"
feature "Pattern of M1.214:32"
feature "Pattern of M1.214:33"
feature "Pattern of M1.214:34"
feature "Pattern of M1.214:35"
feature "Pattern of M1.214:36"
feature "Pattern of M1.214:37"
feature "Pattern of M1.214:38"
feature "Pattern of M1.214:39"
node "M1.225"
node "Cimento"
other parameters: "TIJOLO_PADRAO_COMP" = 240 [user parameter; used in 22 equation terms], "TIJOLO_PADRAO_LARG" = 115 [user parameter; used in 85 equation terms], "TIJOLO_PADRAO_PROF" = 58 [user parameter; used in 7 equation terms], "BLOCO_PADRAO_LARG" = 140 [user parameter; used in 5 equation terms], "AMAR_PADRAO_LARG" = 115 [user parameter; used in 76 equation terms], "AMAR_PADRAO_PROF" = 58 [user parameter], "d231" = -5, "d238" = 15
